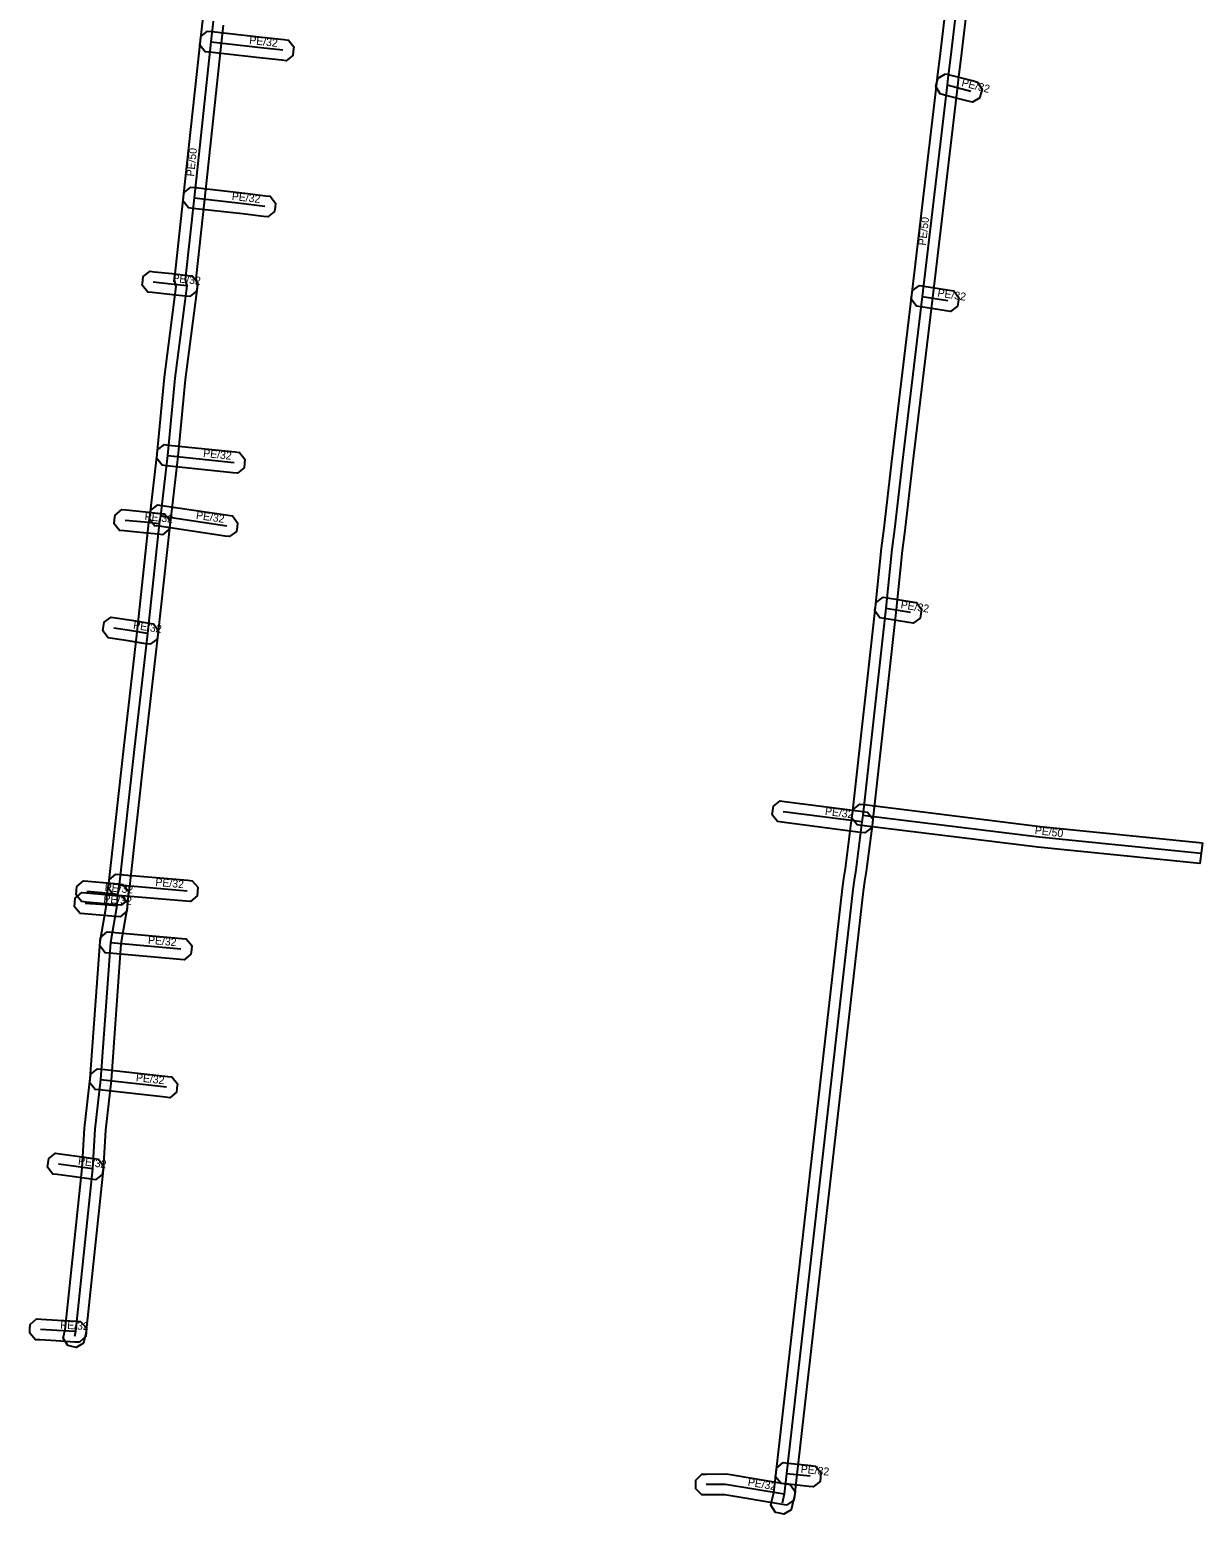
# Model space of a CAD drawing. Extents: x -772893 to -772575, y -1033735 to -1033288.
# Drawn here: x -772707.9 to -772595.6, y -1033584.8 to -1033442.7 of the extents above; entities that cross this region are included whole.
import ezdxf

# ---------------------------------------------------------------- set-up
doc = ezdxf.new("R2010")
doc.units = 0
for name, color, linetype in [('1', 7, 'Continuous'), ('24', 7, 'Continuous'), ('30', 7, 'Continuous')]:
    doc.layers.add(name, color=color, linetype=linetype)

msp = doc.modelspace()

# ---------------------------------------------------------------- linework, layer by layer
at = {"layer": '1'}
for points in [[(-772616.75, -1033428.92), (-772618.7, -1033445.43), (-772618.94, -1033447.43), (-772619.03, -1033448.08), (-772621.4, -1033468.33), (-772623.32, -1033484.24), (-772624.07, -1033490.62), (-772624.31, -1033492.52), (-772624.89, -1033498.17), (-772627.09, -1033517.97), (-772627.17, -1033518.64), (-772627.77, -1033523.25), (-772627.91, -1033524.22), (-772628.05, -1033525.15), (-772634.4, -1033581), (-772634.63, -1033583.04), (-772634.85, -1033583.96), (-772634.94, -1033584.36), (-772635.64, -1033584.8), (-772636.05, -1033584.7), (-772636.45, -1033584.61), (-772636.89, -1033583.91), (-772636.79, -1033583.5), (-772636.61, -1033582.7), (-772636.38, -1033580.78), (-772630.03, -1033524.89), (-772629.89, -1033523.94), (-772629.75, -1033522.97), (-772629.16, -1033518.39), (-772629.07, -1033517.73), (-772626.87, -1033497.95), (-772626.29, -1033492.3), (-772626.05, -1033490.38), (-772625.3, -1033484), (-772623.38, -1033468.09), (-772621.01, -1033447.82), (-772620.92, -1033447.17), (-772620.68, -1033445.19), (-772618.73, -1033428.7)], [(-772689.34, -1033442.23), (-772689.54, -1033443.95), (-772691.14, -1033458.89), (-772691.97, -1033466.51), (-772691.81, -1033467.12), (-772692.97, -1033476.15), (-772693.67, -1033483.53), (-772694.35, -1033489.35), (-772694.46, -1033490.1), (-772695.59, -1033500.57), (-772696.87, -1033511.7), (-772698.31, -1033524.68), (-772698.45, -1033525.57), (-772698.54, -1033526.69), (-772699.14, -1033530.19), (-772700.07, -1033543.27), (-772700.62, -1033548.02), (-772700.84, -1033551.81), (-772702.48, -1033567.48), (-772702.61, -1033568), (-772702.71, -1033568.4), (-772703.42, -1033568.83), (-772703.82, -1033568.73), (-772704.22, -1033568.63), (-772704.65, -1033567.93), (-772704.55, -1033567.52), (-772704.46, -1033567.14), (-772702.84, -1033551.65), (-772702.62, -1033547.84), (-772702.07, -1033543.09), (-772701.12, -1033529.95), (-772700.52, -1033526.44), (-772700.43, -1033525.33), (-772700.29, -1033524.42), (-772698.85, -1033511.48), (-772697.57, -1033500.35), (-772696.44, -1033489.85), (-772696.33, -1033489.09), (-772695.65, -1033483.32), (-772694.95, -1033475.93), (-772693.85, -1033467.24), (-772693.99, -1033466.65), (-772693.12, -1033458.67), (-772691.52, -1033443.73), (-772691.26, -1033441.49)]]:
    msp.add_lwpolyline(points, dxfattribs=at)
for points in [[(-772690.83, -1033442.8), (-772690.42, -1033442.85), (-772685.63, -1033443.38), (-772683.5, -1033443.62), (-772683.09, -1033443.66), (-772682.57, -1033444.31), (-772682.62, -1033444.72), (-772682.66, -1033445.13), (-772683.31, -1033445.65), (-772683.72, -1033445.6), (-772685.85, -1033445.37), (-772690.64, -1033444.83), (-772691.05, -1033444.79), (-772691.57, -1033444.14), (-772691.52, -1033443.73), (-772691.48, -1033443.32)], [(-772620.17, -1033446.88), (-772619.77, -1033446.98), (-772617.49, -1033447.57), (-772617.09, -1033447.68), (-772616.67, -1033448.39), (-772616.77, -1033448.79), (-772616.88, -1033449.19), (-772617.59, -1033449.61), (-772617.99, -1033449.51), (-772620.27, -1033448.92), (-772620.67, -1033448.81), (-772621.09, -1033448.1), (-772620.99, -1033447.7), (-772620.88, -1033447.3)], [(-772692.43, -1033457.74), (-772692.02, -1033457.79), (-772687.27, -1033458.32), (-772685.24, -1033458.56), (-772684.83, -1033458.61), (-772684.32, -1033459.26), (-772684.37, -1033459.67), (-772684.42, -1033460.08), (-772685.07, -1033460.59), (-772685.48, -1033460.54), (-772687.49, -1033460.3), (-772692.24, -1033459.77), (-772692.65, -1033459.73), (-772693.17, -1033459.08), (-772693.12, -1033458.67), (-772693.08, -1033458.26)], [(-772692.53, -1033468.22), (-772692.94, -1033468.17), (-772694.43, -1033468.01), (-772696.15, -1033467.82), (-772696.56, -1033467.78), (-772697.08, -1033467.13), (-772697.03, -1033466.72), (-772696.99, -1033466.31), (-772696.34, -1033465.79), (-772695.93, -1033465.84), (-772694.21, -1033466.02), (-772692.72, -1033466.19), (-772692.31, -1033466.23), (-772691.79, -1033466.88), (-772691.84, -1033467.29), (-772691.88, -1033467.7)], [(-772622.65, -1033467.16), (-772622.24, -1033467.22), (-772619.79, -1033467.6), (-772619.38, -1033467.67), (-772618.89, -1033468.33), (-772618.95, -1033468.74), (-772619.02, -1033469.15), (-772619.68, -1033469.64), (-772620.09, -1033469.58), (-772622.54, -1033469.2), (-772622.95, -1033469.14), (-772623.44, -1033468.47), (-772623.38, -1033468.06), (-772623.32, -1033467.65)], [(-772694.97, -1033482.38), (-772694.56, -1033482.43), (-772688.19, -1033483.09), (-772687.77, -1033483.14), (-772687.25, -1033483.78), (-772687.3, -1033484.2), (-772687.34, -1033484.61), (-772687.98, -1033485.13), (-772688.4, -1033485.09), (-772694.77, -1033484.42), (-772695.18, -1033484.37), (-772695.7, -1033483.73), (-772695.66, -1033483.32), (-772695.61, -1033482.9)], [(-772695.14, -1033491.02), (-772695.55, -1033490.97), (-772696.98, -1033490.83), (-772698.83, -1033490.64), (-772699.25, -1033490.6), (-772699.77, -1033489.96), (-772699.73, -1033489.55), (-772699.69, -1033489.13), (-772699.04, -1033488.61), (-772698.63, -1033488.65), (-772696.78, -1033488.84), (-772695.35, -1033488.98), (-772694.94, -1033489.03), (-772694.41, -1033489.67), (-772694.45, -1033490.08), (-772694.5, -1033490.49)], [(-772695.6, -1033488.17), (-772695.2, -1033488.23), (-772688.85, -1033489.16), (-772688.45, -1033489.22), (-772687.95, -1033489.89), (-772688.01, -1033490.3), (-772688.07, -1033490.71), (-772688.73, -1033491.2), (-772689.15, -1033491.14), (-772695.48, -1033490.21), (-772695.9, -1033490.15), (-772696.39, -1033489.49), (-772696.33, -1033489.08), (-772696.27, -1033488.67)], [(-772626.13, -1033497.01), (-772625.72, -1033497.07), (-772623.36, -1033497.45), (-772622.95, -1033497.52), (-772622.47, -1033498.19), (-772622.53, -1033498.6), (-772622.6, -1033499.01), (-772623.27, -1033499.49), (-772623.68, -1033499.43), (-772626.04, -1033499.05), (-772626.45, -1033498.98), (-772626.93, -1033498.31), (-772626.87, -1033497.9), (-772626.8, -1033497.49)], [(-772696.33, -1033501.51), (-772696.73, -1033501.45), (-772698.43, -1033501.18), (-772699.95, -1033500.95), (-772700.36, -1033500.89), (-772700.85, -1033500.22), (-772700.79, -1033499.81), (-772700.72, -1033499.4), (-772700.06, -1033498.91), (-772699.65, -1033498.97), (-772698.12, -1033499.21), (-772696.43, -1033499.47), (-772696.02, -1033499.54), (-772695.53, -1033500.21), (-772695.59, -1033500.61), (-772695.66, -1033501.02)], [(-772627.88, -1033519.56), (-772628.29, -1033519.51), (-772635.83, -1033518.53), (-772636.24, -1033518.48), (-772636.75, -1033517.82), (-772636.7, -1033517.41), (-772636.64, -1033517), (-772635.99, -1033516.49), (-772635.58, -1033516.55), (-772628.04, -1033517.52), (-772627.63, -1033517.57), (-772627.12, -1033518.23), (-772627.17, -1033518.64), (-772627.23, -1033519.05)], [(-772595.57, -1033520.5), (-772595.8, -1033522.48), (-772611.31, -1033520.93), (-772628.2, -1033518.84), (-772628.61, -1033518.79), (-772629.12, -1033518.14), (-772629.07, -1033517.73), (-772629.02, -1033517.32), (-772628.37, -1033516.81), (-772627.96, -1033516.86), (-772611.09, -1033518.95)], [(-772699.12, -1033526.48), (-772699.53, -1033526.45), (-772701.02, -1033526.31), (-772702.47, -1033526.18), (-772702.89, -1033526.14), (-772703.41, -1033525.5), (-772703.38, -1033525.09), (-772703.34, -1033524.68), (-772702.7, -1033524.15), (-772702.29, -1033524.18), (-772700.84, -1033524.32), (-772699.35, -1033524.45), (-772698.94, -1033524.49), (-772698.41, -1033525.13), (-772698.44, -1033525.54), (-772698.48, -1033525.95)], [(-772699.63, -1033523.52), (-772699.22, -1033523.55), (-772692.72, -1033524.1), (-772692.3, -1033524.14), (-772691.77, -1033524.77), (-772691.8, -1033525.18), (-772691.84, -1033525.6), (-772692.47, -1033526.13), (-772692.88, -1033526.1), (-772699.38, -1033525.55), (-772699.8, -1033525.51), (-772700.33, -1033524.88), (-772700.3, -1033524.47), (-772700.26, -1033524.05)], [(-772699.2, -1033527.59), (-772699.61, -1033527.56), (-772701.15, -1033527.43), (-772702.62, -1033527.31), (-772703.04, -1033527.27), (-772703.57, -1033526.64), (-772703.54, -1033526.23), (-772703.5, -1033525.81), (-772702.87, -1033525.28), (-772702.46, -1033525.31), (-772700.99, -1033525.44), (-772699.45, -1033525.56), (-772699.03, -1033525.6), (-772698.5, -1033526.23), (-772698.53, -1033526.64), (-772698.57, -1033527.06)], [(-772700.45, -1033529.04), (-772700.04, -1033529.07), (-772693.29, -1033529.67), (-772692.88, -1033529.71), (-772692.35, -1033530.35), (-772692.38, -1033530.76), (-772692.42, -1033531.17), (-772693.06, -1033531.7), (-772693.47, -1033531.67), (-772700.22, -1033531.07), (-772700.63, -1033531.03), (-772701.16, -1033530.39), (-772701.13, -1033529.98), (-772701.09, -1033529.57)], [(-772701.37, -1033542.14), (-772700.96, -1033542.19), (-772694.65, -1033542.89), (-772694.24, -1033542.93), (-772693.72, -1033543.58), (-772693.77, -1033543.99), (-772693.81, -1033544.4), (-772694.46, -1033544.92), (-772694.87, -1033544.87), (-772701.18, -1033544.17), (-772701.59, -1033544.13), (-772702.11, -1033543.48), (-772702.06, -1033543.07), (-772702.02, -1033542.66)], [(-772701.57, -1033552.78), (-772701.98, -1033552.72), (-772703.81, -1033552.46), (-772705.23, -1033552.27), (-772705.64, -1033552.22), (-772706.15, -1033551.56), (-772706.09, -1033551.15), (-772706.04, -1033550.74), (-772705.38, -1033550.23), (-772704.97, -1033550.29), (-772703.53, -1033550.48), (-772701.7, -1033550.74), (-772701.29, -1033550.8), (-772700.79, -1033551.46), (-772700.85, -1033551.87), (-772700.91, -1033552.28)], [(-772703.11, -1033568.33), (-772703.53, -1033568.31), (-772705.32, -1033568.2), (-772706.9, -1033568.11), (-772707.32, -1033568.09), (-772707.86, -1033567.47), (-772707.84, -1033567.05), (-772707.82, -1033566.64), (-772707.2, -1033566.09), (-772706.78, -1033566.11), (-772705.2, -1033566.21), (-772703.41, -1033566.31), (-772703, -1033566.34), (-772702.45, -1033566.96), (-772702.47, -1033567.37), (-772702.5, -1033567.78)], [(-772635.7, -1033579.85), (-772635.28, -1033579.9), (-772633.03, -1033580.14), (-772632.61, -1033580.18), (-772632.09, -1033580.82), (-772632.14, -1033581.24), (-772632.18, -1033581.65), (-772632.83, -1033582.17), (-772633.24, -1033582.12), (-772635.5, -1033581.88), (-772635.91, -1033581.84), (-772636.43, -1033581.2), (-772636.38, -1033580.78), (-772636.34, -1033580.37)], [(-772635.38, -1033583.93), (-772635.79, -1033583.86), (-772641.3, -1033582.93), (-772643.08, -1033582.94), (-772643.49, -1033582.94), (-772644.08, -1033582.36), (-772644.08, -1033581.95), (-772644.08, -1033581.53), (-772643.5, -1033580.94), (-772643.08, -1033580.94), (-772641.14, -1033580.93), (-772635.45, -1033581.88), (-772635.05, -1033581.95), (-772634.57, -1033582.63), (-772634.63, -1033583.04), (-772634.7, -1033583.44)]]:
    msp.add_lwpolyline(points, close=True, dxfattribs=at)
at = {"layer": '24'}
for points in [[(-772617.74, -1033428.81), (-772619.69, -1033445.31), (-772619.93, -1033447.3), (-772620.02, -1033447.95), (-772622.39, -1033468.21), (-772624.31, -1033484.12), (-772625.06, -1033490.5), (-772625.3, -1033492.41), (-772625.88, -1033498.06), (-772628.08, -1033517.85), (-772628.17, -1033518.51), (-772628.76, -1033523.11), (-772628.9, -1033524.08), (-772629.04, -1033525.02), (-772635.39, -1033580.89), (-772635.62, -1033582.87), (-772635.82, -1033583.73)], [(-772690.3, -1033441.86), (-772690.53, -1033443.84), (-772692.13, -1033458.78), (-772692.98, -1033466.58), (-772692.83, -1033467.18), (-772693.96, -1033476.04), (-772694.66, -1033483.42), (-772695.34, -1033489.22), (-772695.45, -1033489.98), (-772696.58, -1033500.46), (-772697.86, -1033511.59), (-772699.3, -1033524.55), (-772699.44, -1033525.45), (-772699.53, -1033526.56), (-772700.13, -1033530.07), (-772701.07, -1033543.18), (-772701.62, -1033547.93), (-772701.84, -1033551.73), (-772703.47, -1033567.31), (-772703.58, -1033567.76)], [(-772690.53, -1033443.84), (-772685.74, -1033444.37), (-772683.61, -1033444.61)], [(-772620.02, -1033447.95), (-772617.74, -1033448.54)], [(-772692.13, -1033458.78), (-772687.38, -1033459.31), (-772685.36, -1033459.55)], [(-772692.83, -1033467.18), (-772694.32, -1033467.02), (-772696.04, -1033466.83)], [(-772622.39, -1033468.21), (-772619.94, -1033468.59)], [(-772694.66, -1033483.42), (-772688.29, -1033484.09)], [(-772695.45, -1033489.98), (-772696.88, -1033489.83), (-772698.73, -1033489.65)], [(-772695.34, -1033489.22), (-772689, -1033490.15)], [(-772625.88, -1033498.06), (-772623.52, -1033498.44)], [(-772696.58, -1033500.46), (-772698.28, -1033500.2), (-772699.8, -1033499.96)], [(-772628.17, -1033518.51), (-772635.7, -1033517.54)], [(-772628.08, -1033517.85), (-772611.2, -1033519.94), (-772595.69, -1033521.49)], [(-772699.3, -1033524.55), (-772692.8, -1033525.1)], [(-772699.44, -1033525.45), (-772700.93, -1033525.31), (-772702.38, -1033525.18)], [(-772699.53, -1033526.56), (-772701.07, -1033526.43), (-772702.54, -1033526.31)], [(-772700.13, -1033530.07), (-772693.38, -1033530.67)], [(-772701.07, -1033543.18), (-772694.76, -1033543.88)], [(-772701.84, -1033551.73), (-772703.67, -1033551.47), (-772705.1, -1033551.28)], [(-772703.47, -1033567.31), (-772705.26, -1033567.2), (-772706.84, -1033567.11)], [(-772635.39, -1033580.89), (-772633.13, -1033581.13)], [(-772635.62, -1033582.87), (-772641.22, -1033581.93), (-772643.08, -1033581.94)]]:
    msp.add_lwpolyline(points, dxfattribs=at)

# ---------------------------------------------------------------- texts
at = {"layer": '30'}
for s, rotation, p in [('PE/32', 353.6611, (-772686.87, -1033444.02)), ('PE/32', 345.4917, (-772618.68, -1033448.05)), ('PE/50', 83.8872, (-772692.13, -1033456.75)), ('PE/32', 353.6704, (-772688.54, -1033458.96)), ('PE/50', 83.3279, (-772622.05, -1033463.36)), ('PE/32', 353.8352, (-772694.23, -1033466.8)), ('PE/32', 351.1836, (-772620.97, -1033468.2)), ('PE/32', 353.9957, (-772691.28, -1033483.56)), ('PE/32', 354.2343, (-772696.89, -1033489.61)), ('PE/32', 351.6549, (-772691.97, -1033489.49)), ('PE/32', 350.8529, (-772624.5, -1033498.05)), ('PE/32', 351.1245, (-772697.99, -1033500.01)), ('PE/32', 352.631, (-772631.74, -1033517.83)), ('PE/50', 352.9418, (-772611.65, -1033519.66)), ('PE/32', 354.7536, (-772700.71, -1033525.12)), ('PE/32', 355.1634, (-772695.85, -1033524.63)), ('PE/32', 355.2117, (-772700.83, -1033526.23)), ('PE/32', 354.9204, (-772696.56, -1033530.17)), ('PE/32', 353.6698, (-772697.72, -1033543.33)), ('PE/32', 351.8787, (-772703.27, -1033551.3)), ('PE/32', 356.6035, (-772704.96, -1033567.01)), ('PE/32', 353.9355, (-772634.06, -1033580.81)), ('PE/32', 350.4713, (-772639.14, -1033582.05))]:
    msp.add_text(s, height=0.75, rotation=rotation, dxfattribs=at).set_placement(p)

doc.saveas('drawing.dxf')
